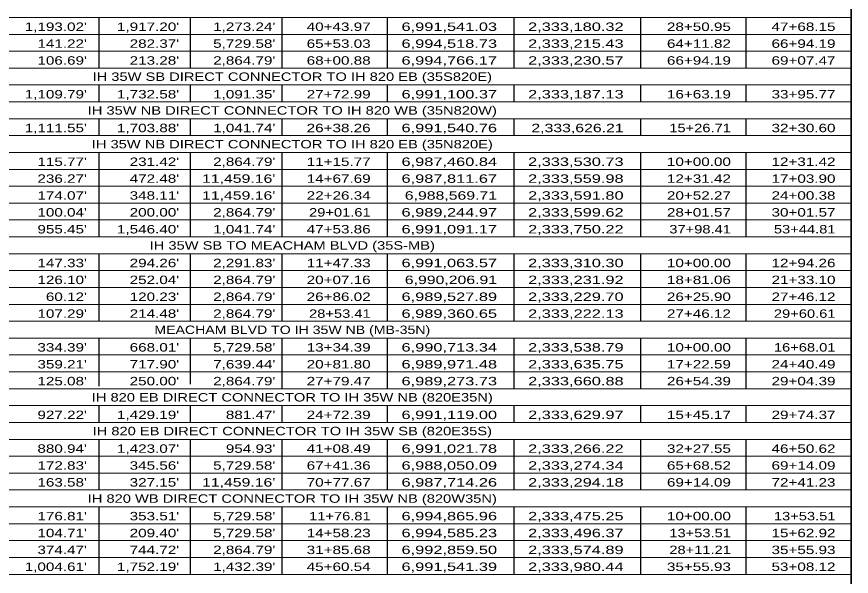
# Model space of a CAD drawing. Extents: x 1953053 to 1967065, y 7363860 to 7371201.
# Drawn here: x 1954423 to 1955610, y 7368565 to 7369361 of the extents above; entities that cross this region are included whole.
import ezdxf
from ezdxf.enums import TextEntityAlignment as Align

# ---------------------------------------------------------------- set-up
doc = ezdxf.new("R2010")
doc.units = 0
doc.header["$LTSCALE"] = 4.8
doc.layers.add('10', color=7, linetype='Continuous')
doc.layers.add('12', color=7, linetype='Continuous', lineweight=25)

msp = doc.modelspace()

# ---------------------------------------------------------------- linework, layer by layer
at = {"layer": '12', "lineweight": 35}
msp.add_line((1955609.815, 7367775.748), (1955609.815, 7370055.746), dxfattribs=at)
at = {"layer": '12', "lineweight": 13}
for p, q in [((1953886.483, 7369359.748), (1955609.815, 7369359.748)), ((1953886.483, 7369335.748), (1955609.815, 7369335.748)), ((1953886.483, 7369311.748), (1955609.815, 7369311.748)), ((1953886.483, 7369287.748), (1955609.815, 7369287.748)), ((1953886.483, 7369263.748), (1955609.815, 7369263.748)), ((1953886.483, 7369239.748), (1955609.815, 7369239.748)), ((1953886.483, 7369215.748), (1955609.815, 7369215.748)), ((1953886.483, 7369191.748), (1955609.815, 7369191.748)), ((1953886.483, 7369167.748), (1955609.815, 7369167.748)), ((1953886.483, 7369143.748), (1955609.815, 7369143.748)), ((1953886.483, 7369119.748), (1955609.815, 7369119.748)), ((1953886.483, 7369095.748), (1955609.815, 7369095.748)), ((1953886.483, 7369071.748), (1955609.815, 7369071.748)), ((1953886.483, 7369047.748), (1955609.815, 7369047.748)), ((1953886.483, 7369023.748), (1955609.815, 7369023.748)), ((1953886.483, 7368999.748), (1955609.815, 7368999.748)), ((1953886.483, 7368975.748), (1955609.815, 7368975.748)), ((1953886.483, 7368951.748), (1955609.815, 7368951.748)), ((1953886.483, 7368927.748), (1955609.815, 7368927.748)), ((1953886.483, 7368903.748), (1955609.815, 7368903.748)), ((1953886.483, 7368879.748), (1955609.815, 7368879.748)), ((1953886.483, 7368855.748), (1955609.815, 7368855.748)), ((1953886.483, 7368831.748), (1955609.815, 7368831.748)), ((1953886.483, 7368807.748), (1955609.815, 7368807.748)), ((1953886.483, 7368783.748), (1955609.815, 7368783.748)), ((1953886.483, 7368759.748), (1955609.815, 7368759.748)), ((1953886.483, 7368735.748), (1955609.815, 7368735.748)), ((1953886.483, 7368711.748), (1955609.815, 7368711.748)), ((1953886.483, 7368687.748), (1955609.815, 7368687.748)), ((1953886.483, 7368663.748), (1955609.815, 7368663.748)), ((1953886.483, 7368639.748), (1955609.815, 7368639.748)), ((1953886.483, 7368615.748), (1955609.815, 7368615.748)), ((1953886.483, 7368591.748), (1955609.815, 7368591.748)), ((1953886.483, 7368567.748), (1955609.815, 7368567.748))]:
    msp.add_line(p, q, dxfattribs=at)
at = {"layer": '12'}
for p, q in [((1954539.815, 7369359.748), (1954539.815, 7369287.748)), ((1954669.815, 7369359.748), (1954669.815, 7369287.748)), ((1954799.815, 7369359.748), (1954799.815, 7369287.748)), ((1954949.815, 7369359.748), (1954949.815, 7369287.748)), ((1955129.815, 7369359.748), (1955129.815, 7369287.748)), ((1955309.815, 7369359.748), (1955309.815, 7369287.748)), ((1955459.815, 7369359.748), (1955459.815, 7369287.748)), ((1954539.815, 7369263.748), (1954539.815, 7369239.748)), ((1954669.815, 7369263.748), (1954669.815, 7369239.748)), ((1954799.815, 7369263.748), (1954799.815, 7369239.748)), ((1954949.815, 7369263.748), (1954949.815, 7369239.748)), ((1955129.815, 7369263.748), (1955129.815, 7369239.748)), ((1955309.815, 7369263.748), (1955309.815, 7369239.748)), ((1955459.815, 7369263.748), (1955459.815, 7369239.748)), ((1954539.815, 7369215.748), (1954539.815, 7369191.748)), ((1954669.815, 7369215.748), (1954669.815, 7369191.748)), ((1954799.815, 7369215.748), (1954799.815, 7369191.748)), ((1954949.815, 7369215.748), (1954949.815, 7369191.748)), ((1955129.815, 7369215.748), (1955129.815, 7369191.748)), ((1955309.815, 7369215.748), (1955309.815, 7369191.748)), ((1955459.815, 7369215.748), (1955459.815, 7369191.748)), ((1954539.815, 7369167.748), (1954539.815, 7369047.748)), ((1954669.815, 7369167.748), (1954669.815, 7369047.748)), ((1954799.815, 7369167.748), (1954799.815, 7369047.748)), ((1954949.815, 7369167.748), (1954949.815, 7369047.748)), ((1955129.815, 7369167.748), (1955129.815, 7369047.748)), ((1955309.815, 7369167.748), (1955309.815, 7369047.748)), ((1955459.815, 7369167.748), (1955459.815, 7369047.748)), ((1954539.815, 7369023.748), (1954539.815, 7368927.748)), ((1954669.815, 7369023.748), (1954669.815, 7368927.748)), ((1954799.815, 7369023.748), (1954799.815, 7368927.748)), ((1954949.815, 7369023.748), (1954949.815, 7368927.748)), ((1955129.815, 7369023.748), (1955129.815, 7368927.748)), ((1955309.815, 7369023.748), (1955309.815, 7368927.748)), ((1955459.815, 7369023.748), (1955459.815, 7368927.748)), ((1954539.815, 7368903.748), (1954539.815, 7368835.145)), ((1954669.815, 7368903.748), (1954669.815, 7368838.378)), ((1954799.815, 7368903.748), (1954799.815, 7368831.748)), ((1954949.815, 7368903.748), (1954949.815, 7368831.748)), ((1955129.815, 7368903.748), (1955129.815, 7368831.748)), ((1955309.815, 7368903.748), (1955309.815, 7368831.748)), ((1955459.815, 7368903.748), (1955459.815, 7368831.748)), ((1954539.815, 7368807.748), (1954539.815, 7368783.748)), ((1954669.815, 7368807.748), (1954669.815, 7368783.748)), ((1954799.815, 7368807.748), (1954799.815, 7368783.748)), ((1954949.815, 7368807.748), (1954949.815, 7368783.748)), ((1955129.815, 7368807.748), (1955129.815, 7368783.748)), ((1955309.815, 7368807.748), (1955309.815, 7368783.748)), ((1955459.815, 7368807.748), (1955459.815, 7368783.748)), ((1954539.815, 7368759.748), (1954539.815, 7368687.748)), ((1954669.815, 7368759.748), (1954669.815, 7368687.748)), ((1954799.815, 7368759.748), (1954799.815, 7368687.748)), ((1954949.815, 7368759.748), (1954949.815, 7368687.748)), ((1955129.815, 7368759.748), (1955129.815, 7368687.748)), ((1955309.815, 7368759.748), (1955309.815, 7368687.748)), ((1955459.815, 7368759.748), (1955459.815, 7368687.748)), ((1954539.815, 7368663.748), (1954539.815, 7368567.748)), ((1954669.815, 7368663.748), (1954669.815, 7368567.748)), ((1954799.815, 7368663.748), (1954799.815, 7368567.748)), ((1954949.815, 7368663.748), (1954949.815, 7368567.748)), ((1955129.815, 7368663.748), (1955129.815, 7368567.748)), ((1955309.815, 7368663.748), (1955309.815, 7368567.748)), ((1955459.815, 7368663.748), (1955459.815, 7368567.748))]:
    msp.add_line(p, q, dxfattribs=at)

# ---------------------------------------------------------------- texts
at = {"layer": '10'}
for s, width, p in [("1,193.02'", 1.35, (1954522.742, 7369340.577)), ("1,917.20'", 1.35, (1954653.939, 7369340.577)), ("1,273.24'", 1.35, (1954790.708, 7369340.577)), ('40+43.97', 1.35, (1954926.252, 7369340.577)), ('6,991,541.03', 1.45, (1955106.017, 7369340.577)), ('2,333,180.32', 1.45, (1955286.017, 7369340.577)), ('28+50.95', 1.35, (1955438.595, 7369340.577)), ('47+68.15', 1.35, (1955587.327, 7369340.577)), ("141.22'", 1.35, (1954522.742, 7369316.577)), ("282.37'", 1.35, (1954653.939, 7369316.577)), ("5,729.58'", 1.35, (1954790.708, 7369316.577)), ('65+53.03', 1.35, (1954926.252, 7369316.577)), ('6,994,518.73', 1.45, (1955106.017, 7369316.577)), ('2,333,215.43', 1.45, (1955286.017, 7369316.577)), ('64+11.82', 1.35, (1955438.595, 7369316.577)), ('66+94.19', 1.35, (1955587.327, 7369316.577)), ("106.69'", 1.35, (1954522.742, 7369292.577)), ("213.28'", 1.35, (1954653.939, 7369292.577)), ("2,864.79'", 1.35, (1954790.708, 7369292.577)), ('68+00.88', 1.35, (1954926.252, 7369292.577)), ('6,994,766.17', 1.45, (1955106.017, 7369292.577)), ('2,333,230.57', 1.45, (1955286.017, 7369292.577)), ('66+94.19', 1.35, (1955438.595, 7369292.577)), ('69+07.47', 1.35, (1955587.327, 7369292.577)), ("1,109.79'", 1.35, (1954522.742, 7369244.577)), ("1,732.58'", 1.35, (1954653.939, 7369244.577)), ("1,091.35'", 1.35, (1954790.708, 7369244.577)), ('27+72.99', 1.35, (1954926.252, 7369244.577)), ('6,991,100.37', 1.45, (1955106.017, 7369244.577)), ('2,333,187.13', 1.45, (1955286.017, 7369244.577)), ('16+63.19', 1.35, (1955438.595, 7369244.577)), ('33+95.77', 1.35, (1955587.327, 7369244.577)), ("1,111.55'", 1.35, (1954522.742, 7369196.577)), ("1,703.88'", 1.35, (1954653.939, 7369196.577)), ("1,041.74'", 1.35, (1954790.708, 7369196.577)), ('26+38.26', 1.35, (1954926.252, 7369196.577)), ('6,991,540.76', 1.45, (1955106.017, 7369196.577)), ('2,333,626.21', 1.4, (1955286.017, 7369196.577)), ('15+26.71', 1.3, (1955438.595, 7369196.577)), ('32+30.60', 1.35, (1955587.327, 7369196.577)), ("115.77'", 1.35, (1954522.742, 7369148.577)), ("231.42'", 1.35, (1954653.939, 7369148.577)), ("2,864.79'", 1.35, (1954790.708, 7369148.577)), ('11+15.77', 1.35, (1954926.252, 7369148.577)), ('6,987,460.84', 1.45, (1955106.017, 7369148.577)), ('2,333,530.73', 1.45, (1955286.017, 7369148.577)), ('10+00.00', 1.35, (1955438.595, 7369148.577)), ('12+31.42', 1.35, (1955587.327, 7369148.577)), ("236.27'", 1.35, (1954522.742, 7369124.577)), ("472.48'", 1.35, (1954653.939, 7369124.577)), ("11,459.16'", 1.4, (1954790.708, 7369124.577)), ('14+67.69', 1.35, (1954926.252, 7369124.577)), ('6,987,811.67', 1.45, (1955106.017, 7369124.577)), ('2,333,559.98', 1.45, (1955286.017, 7369124.577)), ('12+31.42', 1.35, (1955438.595, 7369124.577)), ('17+03.90', 1.35, (1955587.327, 7369124.577)), ("174.07'", 1.35, (1954522.742, 7369100.577)), ("348.11'", 1.35, (1954653.939, 7369100.577)), ("11,459.16'", 1.4, (1954790.708, 7369100.577)), ('22+26.34', 1.35, (1954926.252, 7369100.577)), ('6,988,569.71', 1.4, (1955106.017, 7369100.577)), ('2,333,591.80', 1.45, (1955286.017, 7369100.577)), ('20+52.27', 1.35, (1955438.595, 7369100.577)), ('24+00.38', 1.35, (1955587.327, 7369100.577)), ("100.04'", 1.35, (1954522.742, 7369076.577)), ("200.00'", 1.35, (1954653.939, 7369076.577)), ("2,864.79'", 1.35, (1954790.708, 7369076.577)), ('29+01.61', 1.3, (1954926.252, 7369076.577)), ('6,989,244.97', 1.45, (1955106.017, 7369076.577)), ('2,333,599.62', 1.45, (1955286.017, 7369076.577)), ('28+01.57', 1.35, (1955438.595, 7369076.577)), ('30+01.57', 1.35, (1955587.327, 7369076.577)), ("955.45'", 1.35, (1954522.742, 7369052.577)), ("1,546.40'", 1.35, (1954653.939, 7369052.577)), ("1,041.74'", 1.35, (1954790.708, 7369052.577)), ('47+53.86', 1.35, (1954926.252, 7369052.577)), ('6,991,091.17', 1.45, (1955106.017, 7369052.577)), ('2,333,750.22', 1.45, (1955286.017, 7369052.577)), ('37+98.41', 1.3, (1955438.595, 7369052.577)), ('53+44.81', 1.3, (1955587.327, 7369052.577)), ("147.33'", 1.35, (1954522.742, 7369004.577)), ("294.26'", 1.35, (1954653.939, 7369004.577)), ("2,291.83'", 1.35, (1954790.708, 7369004.577)), ('11+47.33', 1.35, (1954926.252, 7369004.577)), ('6,991,063.57', 1.45, (1955106.017, 7369004.577)), ('2,333,310.30', 1.45, (1955286.017, 7369004.577)), ('10+00.00', 1.35, (1955438.595, 7369004.577)), ('12+94.26', 1.35, (1955587.327, 7369004.577)), ("126.10'", 1.35, (1954522.742, 7368980.577)), ("252.04'", 1.35, (1954653.939, 7368980.577)), ("2,864.79'", 1.35, (1954790.708, 7368980.577)), ('20+07.16', 1.35, (1954926.252, 7368980.577)), ('6,990,206.91', 1.4, (1955106.017, 7368980.577)), ('2,333,231.92', 1.45, (1955286.017, 7368980.577)), ('18+81.06', 1.35, (1955438.595, 7368980.577)), ('21+33.10', 1.35, (1955587.327, 7368980.577)), ("60.12'", 1.35, (1954522.742, 7368956.577)), ("120.23'", 1.35, (1954653.939, 7368956.577)), ("2,864.79'", 1.35, (1954790.708, 7368956.577)), ('26+86.02', 1.35, (1954926.252, 7368956.577)), ('6,989,527.89', 1.45, (1955106.017, 7368956.577)), ('2,333,229.70', 1.45, (1955286.017, 7368956.577)), ('26+25.90', 1.35, (1955438.595, 7368956.577)), ('27+46.12', 1.35, (1955587.327, 7368956.577)), ("107.29'", 1.35, (1954522.742, 7368932.577)), ("214.48'", 1.35, (1954653.939, 7368932.577)), ("2,864.79'", 1.35, (1954790.708, 7368932.577)), ('28+53.41', 1.3, (1954926.252, 7368932.577)), ('6,989,360.65', 1.45, (1955106.017, 7368932.577)), ('2,333,222.13', 1.45, (1955286.017, 7368932.577)), ('27+46.12', 1.35, (1955438.595, 7368932.577)), ('29+60.61', 1.3, (1955587.327, 7368932.577)), ("334.39'", 1.35, (1954522.742, 7368884.577)), ("668.01'", 1.35, (1954653.939, 7368884.577)), ("5,729.58'", 1.35, (1954790.708, 7368884.577)), ('13+34.39', 1.35, (1954926.252, 7368884.577)), ('6,990,713.34', 1.45, (1955106.017, 7368884.577)), ('2,333,538.79', 1.45, (1955286.017, 7368884.577)), ('10+00.00', 1.35, (1955438.595, 7368884.577)), ('16+68.01', 1.3, (1955587.327, 7368884.577)), ("359.21'", 1.35, (1954522.742, 7368860.577)), ("717.90'", 1.35, (1954653.939, 7368860.577)), ("7,639.44'", 1.35, (1954790.708, 7368860.577)), ('20+81.80', 1.35, (1954926.252, 7368860.577)), ('6,989,971.48', 1.45, (1955106.017, 7368860.577)), ('2,333,635.75', 1.45, (1955286.017, 7368860.577)), ('17+22.59', 1.35, (1955438.595, 7368860.577)), ('24+40.49', 1.35, (1955587.327, 7368860.577)), ("125.08'", 1.35, (1954522.742, 7368836.577)), ("250.00'", 1.35, (1954653.939, 7368836.577)), ("2,864.79'", 1.35, (1954790.708, 7368836.577)), ('27+79.47', 1.35, (1954926.252, 7368836.577)), ('6,989,273.73', 1.45, (1955106.017, 7368836.577)), ('2,333,660.88', 1.45, (1955286.017, 7368836.577)), ('26+54.39', 1.35, (1955438.595, 7368836.577)), ('29+04.39', 1.35, (1955587.327, 7368836.577)), ("927.22'", 1.35, (1954522.742, 7368788.577)), ("1,429.19'", 1.35, (1954653.939, 7368788.577)), ("881.47'", 1.35, (1954790.708, 7368788.577)), ('24+72.39', 1.35, (1954926.252, 7368788.577)), ('6,991,119.00', 1.45, (1955106.017, 7368788.577)), ('2,333,629.97', 1.45, (1955286.017, 7368788.577)), ('15+45.17', 1.35, (1955438.595, 7368788.577)), ('29+74.37', 1.35, (1955587.327, 7368788.577)), ("880.94'", 1.35, (1954522.742, 7368740.577)), ("1,423.07'", 1.35, (1954653.939, 7368740.577)), ("954.93'", 1.35, (1954790.708, 7368740.577)), ('41+08.49', 1.35, (1954926.252, 7368740.577)), ('6,991,021.78', 1.45, (1955106.017, 7368740.577)), ('2,333,266.22', 1.45, (1955286.017, 7368740.577)), ('32+27.55', 1.35, (1955438.595, 7368740.577)), ('46+50.62', 1.35, (1955587.327, 7368740.577)), ("172.83'", 1.35, (1954522.742, 7368716.577)), ("345.56'", 1.35, (1954653.939, 7368716.577)), ("5,729.58'", 1.35, (1954790.708, 7368716.577)), ('67+41.36', 1.35, (1954926.252, 7368716.577)), ('6,988,050.09', 1.45, (1955106.017, 7368716.577)), ('2,333,274.34', 1.45, (1955286.017, 7368716.577)), ('65+68.52', 1.35, (1955438.595, 7368716.577)), ('69+14.09', 1.35, (1955587.327, 7368716.577)), ("163.58'", 1.35, (1954522.742, 7368692.577)), ("327.15'", 1.35, (1954653.939, 7368692.577)), ("11,459.16'", 1.4, (1954790.708, 7368692.577)), ('70+77.67', 1.35, (1954926.252, 7368692.577)), ('6,987,714.26', 1.45, (1955106.017, 7368692.577)), ('2,333,294.18', 1.45, (1955286.017, 7368692.577)), ('69+14.09', 1.35, (1955438.595, 7368692.577)), ('72+41.23', 1.35, (1955587.327, 7368692.577)), ("176.81'", 1.35, (1954522.742, 7368644.575)), ("353.51'", 1.35, (1954653.939, 7368644.575)), ("5,729.58'", 1.35, (1954790.708, 7368644.575)), ('11+76.81', 1.3, (1954926.252, 7368644.575)), ('6,994,865.96', 1.45, (1955106.017, 7368644.575)), ('2,333,475.25', 1.45, (1955286.017, 7368644.575)), ('10+00.00', 1.35, (1955438.595, 7368644.575)), ('13+53.51', 1.3, (1955587.327, 7368644.575)), ("104.71'", 1.35, (1954522.742, 7368620.575)), ("209.40'", 1.35, (1954653.939, 7368620.575)), ("5,729.58'", 1.35, (1954790.708, 7368620.575)), ('14+58.23', 1.35, (1954926.252, 7368620.575)), ('6,994,585.23', 1.45, (1955106.017, 7368620.575)), ('2,333,496.37', 1.45, (1955286.017, 7368620.575)), ('13+53.51', 1.3, (1955438.595, 7368620.575)), ('15+62.92', 1.35, (1955587.327, 7368620.575)), ("374.47'", 1.35, (1954522.742, 7368596.575)), ("744.72'", 1.35, (1954653.939, 7368596.575)), ("2,864.79'", 1.35, (1954790.708, 7368596.575)), ('31+85.68', 1.35, (1954926.252, 7368596.575)), ('6,992,859.50', 1.45, (1955106.017, 7368596.575)), ('2,333,574.89', 1.45, (1955286.017, 7368596.575)), ('28+11.21', 1.3, (1955438.595, 7368596.575)), ('35+55.93', 1.35, (1955587.327, 7368596.575)), ("1,004.61'", 1.35, (1954522.742, 7368572.575)), ("1,752.19'", 1.35, (1954653.939, 7368572.575)), ("1,432.39'", 1.35, (1954790.708, 7368572.575)), ('45+60.54', 1.35, (1954926.252, 7368572.575)), ('6,991,541.39', 1.45, (1955106.017, 7368572.575)), ('2,333,980.44', 1.45, (1955286.017, 7368572.575)), ('35+55.93', 1.35, (1955438.595, 7368572.575)), ('53+08.12', 1.35, (1955587.327, 7368572.575))]:
    msp.add_text(s, height=12, dxfattribs=dict(at, width=width)).set_placement(p, align=Align.RIGHT)
for s, width, p in [('IH 35W SB DIRECT CONNECTOR TO IH 820 EB (35S820E)', 1.3, (1954814.815, 7369269.542)), ('IH 35W NB DIRECT CONNECTOR TO IH 820 WB (35N820W)', 1.3, (1954814.815, 7369221.542)), ('IH 35W NB DIRECT CONNECTOR TO IH 820 EB (35N820E)', 1.3, (1954814.815, 7369173.542)), ('IH 35W SB TO MEACHAM BLVD (35S-MB)', 1.3, (1954814.816, 7369029.542)), ('MEACHAM BLVD TO IH 35W NB (MB-35N)', 1.25, (1954814.816, 7368909.542)), ('IH 820 EB DIRECT CONNECTOR TO IH 35W NB (820E35N)', 1.3, (1954814.815, 7368813.542)), ('IH 820 EB DIRECT CONNECTOR TO IH 35W SB (820E35S)', 1.3, (1954814.815, 7368765.542)), ('IH 820 WB DIRECT CONNECTOR TO IH 35W NB (820W35N)', 1.3, (1954814.815, 7368669.542))]:
    msp.add_text(s, height=12, dxfattribs=dict(at, width=width)).set_placement(p, align=Align.CENTER)

doc.saveas('drawing.dxf')
